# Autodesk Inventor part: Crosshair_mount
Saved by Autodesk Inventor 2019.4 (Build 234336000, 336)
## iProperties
Created: 2019-10
Part Number: Crosshair_mount
Material: Generic
Document SubType Name: Modeling
Designer: Administrator
Density: 1 g/cm^3
Appearance: Default
Title: Crosshair_mount
Author: Administrator
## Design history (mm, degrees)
feature "Body1"
body "Solid1"
